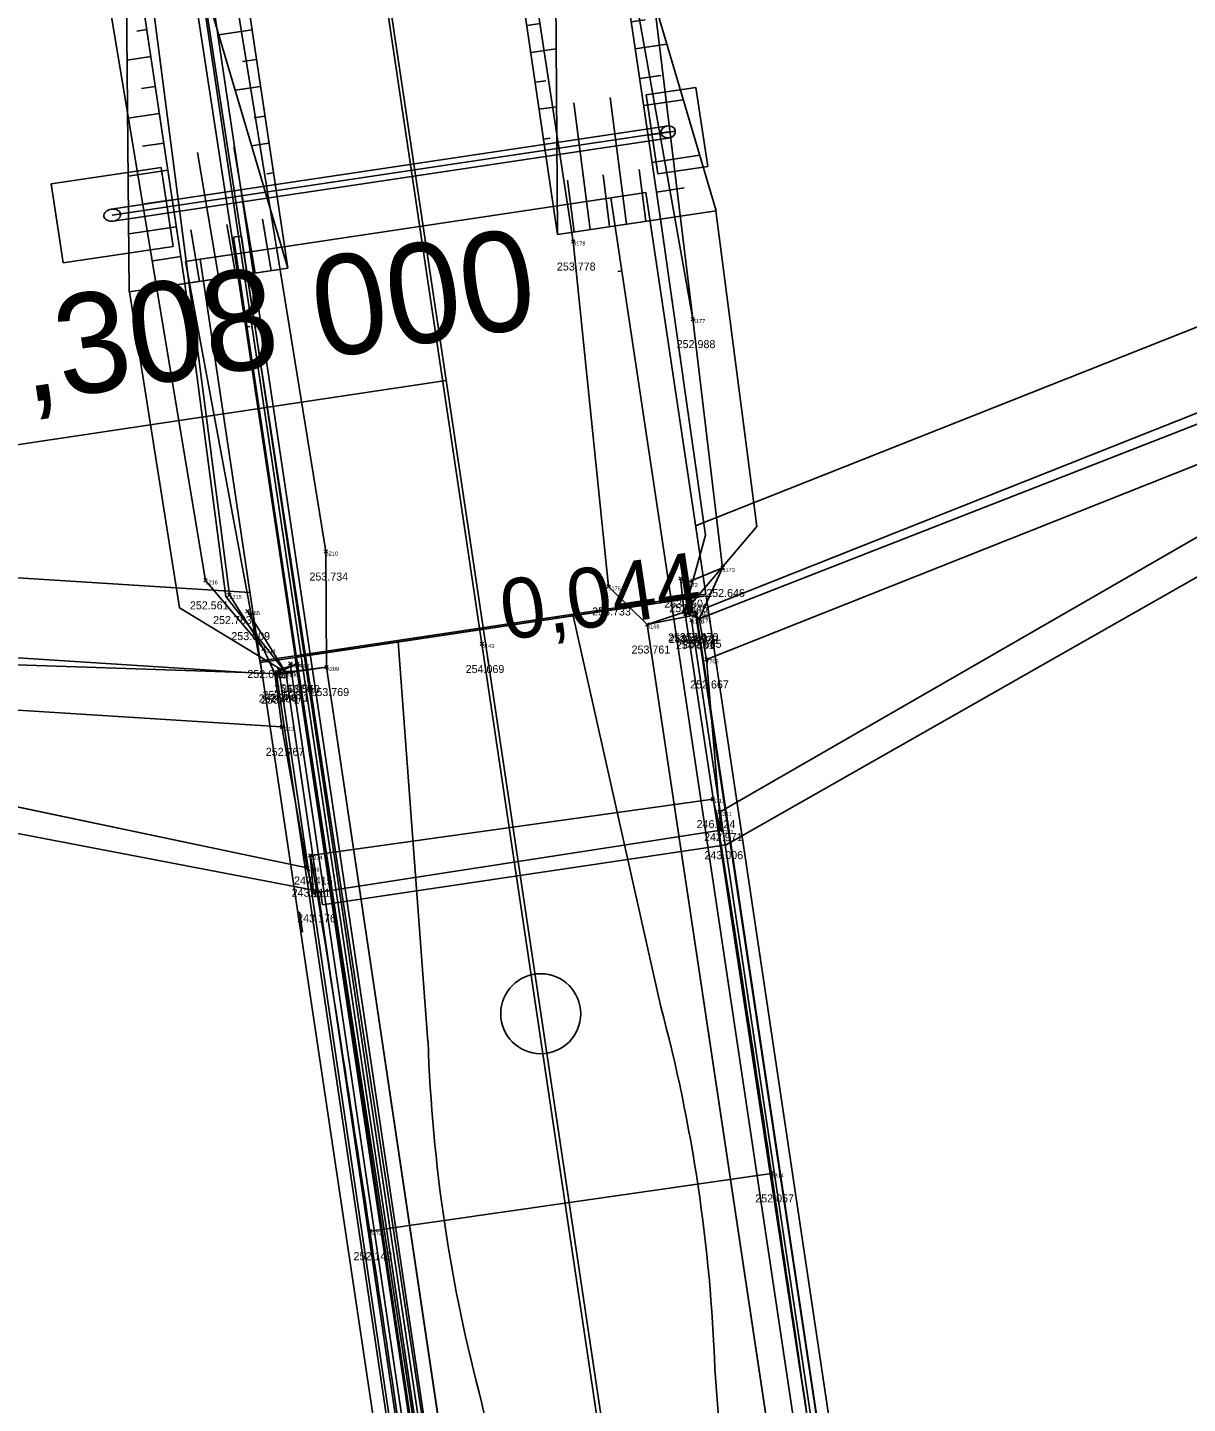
# Model space of a CAD drawing. Extents: x -809973 to -809318, y -1011363 to -1010505.
# Drawn here: x -809871.5 to -809857.01, y -1010848.32 to -1010831.13 of the extents above; entities that cross this region are included whole.
import ezdxf

# ---------------------------------------------------------------- set-up
doc = ezdxf.new("R2010")
doc.units = 0
for name, color, linetype in [('18b - zaměření - čísla bodů', 7, 'Continuous'), ('18c - zaměření - výšky', 7, 'Continuous'), ('Návrh', 7, 'Continuous'), ('SO03 - Železniční svršek', 7, 'Continuous'), ('SO05 - Úprava kabelů', 7, 'Continuous'), ('SO_02', 7, 'Continuous'), ('stav_stav', 7, 'Continuous'), ('žel svršek_hrany', 7, 'Continuous')]:
    doc.layers.add(name, color=color, linetype=linetype)

# ---------------------------------------------------------------- blocks, each defined once
blk = doc.blocks.new('POINT_DISPLAY')
for p, q in [((-0.021, -0.021), (0.021, 0.021)), ((-0.021, 0.021), (0.021, -0.021))]:
    blk.add_line(p, q)
blk = doc.blocks.new('rampa')
at = {"layer": 'žel svršek_hrany'}
for p, q in [((-790324.322, -1020004.416), (-790323.604, -1020002.55)), ((-790323.604, -1020002.55), (-790322.95, -1020002.801)), ((-790325.466, -1020009.334), (-790322.95, -1020002.801)), ((-790323.095, -1020003.177), (-790323.748, -1020002.926)), ((-790323.223, -1020003.51), (-790323.55, -1020003.384)), ((-790323.353, -1020003.846), (-790324.006, -1020003.595)), ((-790323.488, -1020004.197), (-790323.814, -1020004.071)), ((-790322.323, -1020010.631), (-790319.799, -1020004.102)), ((-790319.146, -1020004.354), (-790319.799, -1020004.102)), ((-790327.333, -1020008.615), (-790324.882, -1020004.201)), ((-790326.679, -1020008.867), (-790324.882, -1020004.201)), ((-790324.882, -1020004.201), (-790324.322, -1020004.416)), ((-790323.611, -1020004.515), (-790324.264, -1020004.264)), ((-790324.322, -1020004.416), (-790325.466, -1020009.334)), ((-790319.944, -1020004.478), (-790319.291, -1020004.73)), ((-790319.867, -1020006.22), (-790319.146, -1020004.354)), ((-790323.745, -1020004.866), (-790324.072, -1020004.74)), ((-790320.072, -1020004.81), (-790319.746, -1020004.936)), ((-790323.868, -1020005.184), (-790324.449, -1020004.961)), ((-790320.203, -1020005.146), (-790319.55, -1020005.399)), ((-790325.391, -1020005.522), (-790325.576, -1020005.45)), ((-790324.003, -1020005.535), (-790324.33, -1020005.409)), ((-790320.338, -1020005.496), (-790320.011, -1020005.623)), ((-790324.126, -1020005.853), (-790324.613, -1020005.666)), ((-790325.526, -1020005.872), (-790325.643, -1020005.827)), ((-790320.461, -1020005.815), (-790319.808, -1020006.067)), ((-790325.649, -1020006.191), (-790325.927, -1020006.083)), ((-790325.649, -1020006.191), (-790325.927, -1020006.083)), ((-790324.261, -1020006.204), (-790324.424, -1020006.141)), ((-790319.867, -1020006.22), (-790322.323, -1020010.631)), ((-790320.596, -1020006.165), (-790320.27, -1020006.291)), ((-790319.307, -1020006.436), (-790319.867, -1020006.22)), ((-790324.383, -1020006.522), (-790324.777, -1020006.371)), ((-790325.784, -1020006.541), (-790325.947, -1020006.478)), ((-790321.11, -1020011.1), (-790319.307, -1020006.436)), ((-790320.72, -1020006.484), (-790320.139, -1020006.708)), ((-790320.457, -1020011.352), (-790319.307, -1020006.436)), ((-790325.906, -1020006.86), (-790326.279, -1020006.716)), ((-790325.906, -1020006.86), (-790326.279, -1020006.716)), ((-790324.518, -1020006.873), (-790324.682, -1020006.81)), ((-790320.855, -1020006.834), (-790320.528, -1020006.96)), ((-790324.641, -1020007.191), (-790324.941, -1020007.076)), ((-790326.041, -1020007.21), (-790326.29, -1020007.114)), ((-790320.978, -1020007.152), (-790320.491, -1020007.341)), ((-790326.164, -1020007.529), (-790326.63, -1020007.349)), ((-790326.164, -1020007.529), (-790326.63, -1020007.349)), ((-790326.278, -1020009.021), (-790325.731, -1020007.52)), ((-790324.776, -1020007.542), (-790324.901, -1020007.493)), ((-790321.113, -1020007.502), (-790320.95, -1020007.565)), ((-790326.299, -1020007.879), (-790326.626, -1020007.753)), ((-790325.85, -1020009.186), (-790325.303, -1020007.685)), ((-790319.818, -1020007.756), (-790319.633, -1020007.828)), ((-790324.899, -1020007.86), (-790325.105, -1020007.781)), ((-790321.236, -1020007.821), (-790320.843, -1020007.973)), ((-790326.422, -1020008.198), (-790326.981, -1020007.982)), ((-790326.422, -1020008.198), (-790326.981, -1020007.982)), ((-790319.953, -1020008.106), (-790319.836, -1020008.152)), ((-790325.034, -1020008.211), (-790325.112, -1020008.18)), ((-790321.372, -1020008.171), (-790321.209, -1020008.234)), ((-790326.557, -1020008.548), (-790326.883, -1020008.422)), ((-790326.506, -1020008.933), (-790326.284, -1020008.32)), ((-790320.076, -1020008.425), (-790319.798, -1020008.533)), ((-790320.076, -1020008.425), (-790319.798, -1020008.533)), ((-790325.466, -1020009.334), (-790327.333, -1020008.615)), ((-790325.466, -1020009.334), (-790327.333, -1020008.615)), ((-790326.078, -1020009.098), (-790325.856, -1020008.484)), ((-790321.495, -1020008.49), (-790321.195, -1020008.605)), ((-790325.66, -1020009.259), (-790325.438, -1020008.645)), ((-790320.212, -1020008.775), (-790320.048, -1020008.838)), ((-790321.63, -1020008.84), (-790321.505, -1020008.888)), ((-790320.335, -1020009.094), (-790319.963, -1020009.237)), ((-790320.335, -1020009.094), (-790319.963, -1020009.237)), ((-790321.939, -1020010.779), (-790321.336, -1020009.3)), ((-790321.753, -1020009.158), (-790321.547, -1020009.238)), ((-790321.511, -1020010.945), (-790320.909, -1020009.465)), ((-790320.47, -1020009.444), (-790320.222, -1020009.54)), ((-790321.889, -1020009.508), (-790321.81, -1020009.539)), ((-790320.593, -1020009.762), (-790320.127, -1020009.942)), ((-790320.593, -1020009.762), (-790320.127, -1020009.942)), ((-790322.129, -1020010.706), (-790321.881, -1020010.102)), ((-790320.729, -1020010.112), (-790320.402, -1020010.239)), ((-790321.711, -1020010.867), (-790321.463, -1020010.264)), ((-790321.284, -1020011.033), (-790321.036, -1020010.429)), ((-790320.852, -1020010.431), (-790320.292, -1020010.647)), ((-790320.852, -1020010.431), (-790320.292, -1020010.647)), ((-790322.323, -1020010.631), (-790320.457, -1020011.352)), ((-790322.323, -1020010.631), (-790320.457, -1020011.352)), ((-790320.987, -1020010.781), (-790320.661, -1020010.907))]:
    blk.add_line(p, q, dxfattribs=at)

msp = doc.modelspace()

# ---------------------------------------------------------------- linework, layer by layer
at = {"layer": 'Návrh'}
msp.add_line((-809857.286, -1010895.613), (-809869.822, -1010811.804), dxfattribs=at)
msp.add_circle((-809865.089, -1010843.452), 0.5, dxfattribs=at)
at = {"layer": 'SO03 - Železniční svršek'}
for p, q in [((-809863.591, -1010833.524), (-809863.028, -1010837.471)), ((-809862.899, -1010833.421), (-809862.388, -1010837.366)), ((-809868.251, -1010834.137), (-809869.636, -1010834.345)), ((-809870.229, -1010834.433), (-809869.603, -1010838.382)), ((-809866.272, -1010835.54), (-809888.524, -1010838.869)), ((-809862.388, -1010837.366), (-809863.296, -1010838.436)), ((-809863.028, -1010837.471), (-809863.296, -1010838.436)), ((-809869.603, -1010838.382), (-809868.277, -1010839.183))]:
    msp.add_line(p, q, dxfattribs=at)
for points in [[(-809862, -1010879.706), (-809862.476, -1010876.825), (-809862.419, -1010876.062), (-809862.279, -1010876.008), (-809867.764, -1010839.12), (-809868.277, -1010839.183), (-809869.024, -1010838.237), (-809869.537, -1010834.33)], [(-809863.296, -1010838.436), (-809863.759, -1010838.589), (-809858.21, -1010875.554)]]:
    msp.add_lwpolyline(points, dxfattribs=at)
at = {"layer": 'SO05 - Úprava kabelů'}
for points in [[(-809832.494, -1011018.409), (-809834.046, -1011017.811), (-809840.102, -1011020.003), (-809840.886, -1011019.699), (-809849.784, -1011002.747), (-809854.105, -1010999.74), (-809859.871, -1010979.608), (-809861.054, -1010971.463), (-809873.181, -1010917.053), (-809875.79, -1010892.925), (-809862.192, -1010877.803), (-809870.3, -1010824.924)], [(-809832.452, -1011018.3), (-809834.045, -1011017.686), (-809840.101, -1011019.878), (-809840.803, -1011019.606), (-809849.694, -1011002.668), (-809854.004, -1010999.668), (-809859.756, -1010979.584), (-809860.94, -1010971.442), (-809873.066, -1010917.034), (-809875.669, -1010892.964), (-809862.069, -1010877.84), (-809862.069, -1010877.84), (-809870.184, -1010824.906)], [(-809832.452, -1011018.3), (-809834.599, -1011012.541), (-809836.558, -1011007.657), (-809839.63, -1011000.177), (-809840.754, -1010995.474), (-809845.885, -1010976.431), (-809847.466, -1010970.457), (-809849.998, -1010958.97), (-809853.746, -1010939.574), (-809862.448, -1010886.367), (-809861.681, -1010881.903), (-809870.184, -1010824.906)], [(-809832.343, -1011018.259), (-809834.49, -1011012.499), (-809836.45, -1011007.613), (-809839.519, -1011000.141), (-809840.641, -1010995.445), (-809845.773, -1010976.401), (-809847.353, -1010970.429), (-809849.884, -1010958.947), (-809853.631, -1010939.554), (-809862.33, -1010886.367), (-809861.563, -1010881.905), (-809870.069, -1010824.889)]]:
    msp.add_lwpolyline(points, dxfattribs=at)
at = {"layer": 'SO_02'}
for p, q in [((-809863.149, -1010831.878), (-809863.772, -1010831.971)), ((-809863.625, -1010832.96), (-809863.772, -1010831.971)), ((-809863.001, -1010832.867), (-809863.149, -1010831.878)), ((-809863.494, -1010832.359), (-809870.455, -1010833.4)), ((-809863.496, -1010832.435), (-809870.443, -1010833.474)), ((-809863.472, -1010832.508), (-809870.432, -1010833.549)), ((-809869.83, -1010832.877), (-809871.205, -1010833.083)), ((-809869.682, -1010833.866), (-809869.83, -1010832.877)), ((-809863.001, -1010832.867), (-809863.625, -1010832.96)), ((-809852.025, -1010832.942), (-809863.154, -1010837.357)), ((-809871.057, -1010834.072), (-809871.205, -1010833.083)), ((-809864.212, -1010833.257), (-809863.777, -1010833.192)), ((-809863.026, -1010838.211), (-809863.777, -1010833.192)), ((-809864.212, -1010833.257), (-809868.91, -1010833.96)), ((-809863.461, -1010838.277), (-809864.212, -1010833.257)), ((-809868.827, -1010833.736), (-809868.926, -1010833.75)), ((-809861.648, -1010881.731), (-809868.827, -1010833.736)), ((-809869.682, -1010833.866), (-809871.057, -1010834.072)), ((-809861.747, -1010881.746), (-809868.926, -1010833.75)), ((-809851.656, -1010833.871), (-809863.002, -1010838.373)), ((-809869.345, -1010834.025), (-809869.528, -1010834.052)), ((-809869.528, -1010834.052), (-809868.571, -1010839.2)), ((-809869.345, -1010834.025), (-809868.91, -1010833.96)), ((-809868.594, -1010839.044), (-809869.345, -1010834.025)), ((-809868.159, -1010838.979), (-809868.91, -1010833.96)), ((-809864.125, -1010834.18), (-809864.075, -1010834.172)), ((-809851.435, -1010834.429), (-809863.019, -1010839.025)), ((-809868.723, -1010834.867), (-809868.773, -1010834.875)), ((-809851.284, -1010834.811), (-809862.773, -1010841.34)), ((-809879.74, -1010837.49), (-809868.722, -1010838.188)), ((-809863.461, -1010838.277), (-809868.159, -1010838.979)), ((-809863.458, -1010838.296), (-809868.156, -1010838.999)), ((-809868.149, -1010838.996), (-809863.639, -1010838.324)), ((-809863.461, -1010838.277), (-809863.026, -1010838.211)), ((-809863.458, -1010838.296), (-809863.023, -1010838.231)), ((-809857.874, -1010875.633), (-809863.458, -1010838.296)), ((-809857.438, -1010875.568), (-809863.023, -1010838.231)), ((-809879.803, -1010838.488), (-809868.571, -1010839.2)), ((-809863.588, -1010843.366), (-809864.684, -1010838.48)), ((-809863.296, -1010838.436), (-809863.109, -1010838.517)), ((-809863.285, -1010838.455), (-809863.296, -1010838.436)), ((-809863.285, -1010838.455), (-809857.753, -1010874.863)), ((-809857.7, -1010874.685), (-809863.148, -1010838.433)), ((-809863.109, -1010838.517), (-809863.019, -1010839.025)), ((-809866.872, -1010838.806), (-809866.498, -1010843.8)), ((-809868.594, -1010839.044), (-809868.159, -1010838.979)), ((-809868.591, -1010839.064), (-809868.156, -1010838.999)), ((-809863.006, -1010876.401), (-809868.591, -1010839.064)), ((-809867.488, -1010838.899), (-809868.156, -1010838.999)), ((-809862.571, -1010876.336), (-809868.156, -1010838.999)), ((-809863.019, -1010839.025), (-809862.853, -1010840.932)), ((-809879.844, -1010839.137), (-809868.322, -1010839.867)), ((-809868.363, -1010839.157), (-809862.976, -1010875.541)), ((-809867.839, -1010841.924), (-809879.909, -1010839.613)), ((-809868.322, -1010839.867), (-809868.007, -1010841.627)), ((-809867.969, -1010841.475), (-809862.938, -1010840.77)), ((-809862.773, -1010841.34), (-809867.814, -1010842.091)), ((-809867.814, -1010842.091), (-809867.839, -1010841.924)), ((-809868.066, -1010842.432), (-809868.104, -1010842.179)), ((-809867.226, -1010846.168), (-809862.205, -1010845.446)), ((-809862.914, -1010847.888), (-809862.647, -1010851.434)), ((-809865.044, -1010851.791), (-809865.824, -1010848.321))]:
    msp.add_line(p, q, dxfattribs=at)
for points in [[(-809851.664, -1010834.047), (-809851.435, -1010834.429), (-809852.346, -1010834.881), (-809862.853, -1010840.932), (-809862.84, -1010841.158), (-809862.938, -1010840.77)], [(-809863.285, -1010838.455), (-809863.148, -1010838.433)], [(-809863.152, -1010838.466), (-809863.148, -1010838.433)], [(-809867.929, -1010841.946), (-809868.007, -1010841.627), (-809878.719, -1010839.38), (-809879.844, -1010839.137), (-809879.859, -1010838.825)], [(-809868.39, -1010839.215), (-809868.363, -1010839.157)], [(-809868.129, -1010839.082), (-809868.363, -1010839.157)], [(-809867.969, -1010841.475), (-809867.929, -1010841.946), (-809862.84, -1010841.158)]]:
    msp.add_lwpolyline(points, dxfattribs=at)
for centre, radius, start, end in [((-809883.074, -1010848.581), 20.172, 1.9683, 14.9818), ((-809846.356, -1010843.109), 20.153, 181.9622, 194.988)]:
    msp.add_arc(centre, radius, start, end, dxfattribs=at)
for centre, major_axis, ratio in [((-809863.496, -1010832.435), (-0.089, -0.0133), 0.841589), ((-809870.443, -1010833.474), (0.104, 0.016), 0.714286)]:
    msp.add_ellipse(centre, major_axis=major_axis, ratio=ratio, dxfattribs=at)
for centre, major_axis, ratio, start_param, end_param in [((-809862.233, -1010845.48), (-0.705, 4.723), 0.006805, 3.144401, 6.358135), ((-809867.249, -1010846.221), (0.72, -4.746), 0.006491, 6.194401, 9.4095)]:
    msp.add_ellipse(centre, major_axis=major_axis, ratio=ratio, start_param=start_param, end_param=end_param, dxfattribs=at)
at = {"layer": 'stav_stav'}
for p, q in [((-809864.684, -1010833.803), (-809870.275, -1010797.222)), ((-809865.824, -1010838.832), (-809869.271, -1010815.693)), ((-809863.187, -1010834.773), (-809864.375, -1010825.057)), ((-809863.187, -1010834.773), (-809864.88, -1010825.285)), ((-809867.776, -1010837.677), (-809868.98, -1010830.232)), ((-809869.278, -1010838.037), (-809870.544, -1010830.445)), ((-809868.98, -1010838.22), (-809869.985, -1010830.456)), ((-809864.243, -1010838.113), (-809864.684, -1010833.803)), ((-809863.109, -1010838.517), (-809851.664, -1010834.047)), ((-809863.109, -1010838.517), (-809851.664, -1010834.047)), ((-809851.435, -1010834.429), (-809863.019, -1010839.025)), ((-809862.818, -1010837.882), (-809863.187, -1010834.773)), ((-809862.818, -1010837.882), (-809863.187, -1010834.773)), ((-809852.346, -1010834.881), (-809862.853, -1010840.932)), ((-809867.764, -1010839.12), (-809867.776, -1010837.677)), ((-809868.553, -1010838.894), (-809869.278, -1010838.037)), ((-809863.296, -1010838.436), (-809863.342, -1010838.015)), ((-809863.342, -1010838.015), (-809863.28, -1010838.072)), ((-809863.28, -1010838.072), (-809862.818, -1010837.882)), ((-809863.109, -1010838.517), (-809862.818, -1010837.882)), ((-809863.759, -1010838.589), (-809864.243, -1010838.113)), ((-809868.553, -1010838.894), (-809868.98, -1010838.22)), ((-809868.752, -1010838.421), (-809868.273, -1010839.19)), ((-809863.759, -1010838.589), (-809863.296, -1010838.436)), ((-809863.759, -1010838.589), (-809863.296, -1010838.436)), ((-809863.152, -1010838.466), (-809863.759, -1010838.589)), ((-809863.296, -1010838.436), (-809863.109, -1010838.517)), ((-809863.285, -1010838.455), (-809863.296, -1010838.436)), ((-809863.285, -1010838.455), (-809863.148, -1010838.433)), ((-809863.285, -1010838.455), (-809857.753, -1010874.863)), ((-809863.205, -1010838.533), (-809857.614, -1010875.806)), ((-809863.152, -1010838.466), (-809863.148, -1010838.433)), ((-809857.691, -1010874.74), (-809863.152, -1010838.466)), ((-809857.7, -1010874.685), (-809863.148, -1010838.433)), ((-809863.109, -1010838.517), (-809863.019, -1010839.025)), ((-809858.211, -1010875.546), (-809863.759, -1010838.589)), ((-809863.759, -1010838.589), (-809858.211, -1010875.546)), ((-809868.41, -1010839.199), (-809879.859, -1010838.825)), ((-809868.41, -1010839.199), (-809879.859, -1010838.825)), ((-809868.41, -1010839.199), (-809868.553, -1010838.894)), ((-809868.41, -1010839.199), (-809868.553, -1010838.894)), ((-809863.238, -1010856.222), (-809865.824, -1010838.832)), ((-809863.019, -1010839.025), (-809862.853, -1010840.932)), ((-809879.844, -1010839.137), (-809868.322, -1010839.867)), ((-809868.129, -1010839.082), (-809868.41, -1010839.199)), ((-809867.764, -1010839.12), (-809868.41, -1010839.199)), ((-809867.764, -1010839.12), (-809868.41, -1010839.199)), ((-809868.41, -1010839.199), (-809868.322, -1010839.867)), ((-809867.764, -1010839.12), (-809868.39, -1010839.215)), ((-809868.39, -1010839.215), (-809868.363, -1010839.157)), ((-809862.989, -1010875.64), (-809868.39, -1010839.215)), ((-809868.129, -1010839.082), (-809868.363, -1010839.157)), ((-809868.363, -1010839.157), (-809862.976, -1010875.541)), ((-809868.273, -1010839.19), (-809862.71, -1010876.93)), ((-809868.218, -1010839.075), (-809862.732, -1010876.12)), ((-809862.279, -1010876.008), (-809867.764, -1010839.12)), ((-809862.279, -1010876.008), (-809867.764, -1010839.12)), ((-809868.007, -1010841.627), (-809878.719, -1010839.38)), ((-809868.322, -1010839.867), (-809868.007, -1010841.627)), ((-809862.84, -1010841.158), (-809862.938, -1010840.77)), ((-809862.853, -1010840.932), (-809862.84, -1010841.158)), ((-809867.929, -1010841.946), (-809862.84, -1010841.158)), ((-809867.969, -1010841.475), (-809867.929, -1010841.946)), ((-809867.929, -1010841.946), (-809868.007, -1010841.627)), ((-809867.226, -1010846.168), (-809862.205, -1010845.446))]:
    msp.add_line(p, q, dxfattribs=at)
for centre, major_axis, ratio, start_param, end_param in [((-809862.233, -1010845.48), (-0.705, 4.723), 0.006805, 3.144401, 6.358135), ((-809867.249, -1010846.221), (0.72, -4.746), 0.006491, 6.194401, 9.4095)]:
    msp.add_ellipse(centre, major_axis=major_axis, ratio=ratio, start_param=start_param, end_param=end_param, dxfattribs=at)

# ---------------------------------------------------------------- block references
at = {"layer": '18b - zaměření - čísla bodů'}
for p in [(-809864.684, -1010833.803), (-809863.187, -1010834.773), (-809867.776, -1010837.677), (-809862.818, -1010837.882), (-809869.278, -1010838.037), (-809863.342, -1010838.015), (-809868.98, -1010838.22), (-809864.243, -1010838.113), (-809863.28, -1010838.072), (-809868.752, -1010838.421), (-809863.296, -1010838.436), (-809863.285, -1010838.455), (-809863.205, -1010838.533), (-809863.152, -1010838.466), (-809863.148, -1010838.433), (-809863.109, -1010838.517), (-809863.759, -1010838.589), (-809868.553, -1010838.894), (-809865.824, -1010838.832), (-809868.218, -1010839.075), (-809868.129, -1010839.082), (-809863.019, -1010839.025), (-809868.41, -1010839.199), (-809868.39, -1010839.215), (-809868.363, -1010839.157), (-809868.273, -1010839.19), (-809867.764, -1010839.12), (-809868.322, -1010839.867), (-809862.938, -1010840.77), (-809862.853, -1010840.932), (-809862.84, -1010841.158), (-809867.969, -1010841.475), (-809868.007, -1010841.627), (-809867.929, -1010841.946), (-809862.205, -1010845.446), (-809867.226, -1010846.168)]:
    msp.add_blockref('POINT_DISPLAY', p, dxfattribs=at)
at = {"layer": 'žel svršek_hrany', "rotation": 29.569690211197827}
msp.add_blockref('rampa', (-625833.924, 266336.466), dxfattribs=at)

# ---------------------------------------------------------------- texts
at = {"layer": '18b - zaměření - čísla bodů'}
for s, p in [('5178', (-809864.684, -1010833.853)), ('5177', (-809863.187, -1010834.823)), ('5210', (-809867.776, -1010837.727)), ('5216', (-809869.278, -1010838.087)), ('5171', (-809863.342, -1010838.065)), ('5173', (-809862.818, -1010837.932)), ('5176', (-809864.243, -1010838.163)), ('5172', (-809863.28, -1010838.122)), ('5215', (-809868.98, -1010838.27)), ('5185', (-809868.752, -1010838.471)), ('5170', (-809863.296, -1010838.486)), ('7703', (-809863.285, -1010838.505)), ('5149', (-809863.205, -1010838.583)), ('5169', (-809863.152, -1010838.516)), ('7704', (-809863.148, -1010838.483)), ('5174', (-809863.109, -1010838.567)), ('5168', (-809863.759, -1010838.639)), ('5214', (-809868.553, -1010838.944)), ('5143', (-809865.824, -1010838.882)), ('7706', (-809863.019, -1010839.075)), ('5212', (-809868.41, -1010839.249)), ('5211', (-809868.39, -1010839.265)), ('7708', (-809868.363, -1010839.207)), ('5186', (-809868.273, -1010839.24)), ('5184', (-809868.218, -1010839.125)), ('7707', (-809868.129, -1010839.132)), ('5209', (-809867.764, -1010839.17)), ('5213', (-809868.322, -1010839.917)), ('5313', (-809862.938, -1010840.82)), ('5311', (-809862.853, -1010840.982)), ('5312', (-809862.84, -1010841.208)), ('5274', (-809867.969, -1010841.525)), ('5298', (-809868.007, -1010841.677)), ('5297', (-809867.929, -1010841.996)), ('5314', (-809862.205, -1010845.496)), ('5273', (-809867.226, -1010846.218))]:
    msp.add_text(s, height=0.05, dxfattribs=at).set_placement(p)
at = {"layer": '18c - zaměření - výšky'}
for s, p in [('253.778', (-809864.887, -1010834.166)), ('252.988', (-809863.39, -1010835.136)), ('253.734', (-809867.979, -1010838.04)), ('252.646', (-809863.021, -1010838.245)), ('252.561', (-809869.473, -1010838.4)), ('253.733', (-809864.446, -1010838.476)), ('253.250', (-809863.545, -1010838.378)), ('252.846', (-809863.483, -1010838.435)), ('252.783', (-809869.183, -1010838.583)), ('253.009', (-809868.955, -1010838.784)), ('253.380', (-809863.499, -1010838.799)), ('253.480', (-809863.488, -1010838.818)), ('253.470', (-809863.351, -1010838.796)), ('253.761', (-809863.954, -1010838.952)), ('254.881', (-809863.4, -1010838.896)), ('253.723', (-809863.355, -1010838.829)), ('252.685', (-809863.312, -1010838.88)), ('252.692', (-809868.755, -1010839.257)), ('254.069', (-809866.027, -1010839.195)), ('254.900', (-809868.421, -1010839.438)), ('253.550', (-809868.332, -1010839.445)), ('253.769', (-809867.967, -1010839.483)), ('252.667', (-809863.222, -1010839.388)), ('252.784', (-809868.613, -1010839.562)), ('253.771', (-809868.585, -1010839.578)), ('253.538', (-809868.566, -1010839.52)), ('254.071', (-809868.468, -1010839.553)), ('252.767', (-809868.525, -1010840.23)), ('246.924', (-809863.141, -1010841.133)), ('242.971', (-809863.048, -1010841.295)), ('243.006', (-809863.043, -1010841.521)), ('247.415', (-809868.172, -1010841.838)), ('243.111', (-809868.202, -1010841.99)), ('243.176', (-809868.132, -1010842.309)), ('252.057', (-809862.408, -1010845.809)), ('252.142', (-809867.428, -1010846.531))]:
    msp.add_text(s, height=0.1, dxfattribs=at).set_placement(p)
at = {"layer": 'SO03 - Železniční svršek'}
for s, height, p in [('km 190,308 000', 1.25, (-809876.945, -1010836.631)), ('0,044', 0.75, (-809865.533, -1010838.789))]:
    msp.add_text(s, height=height, rotation=8.5071, dxfattribs=at).set_placement(p)

doc.saveas('drawing.dxf')
